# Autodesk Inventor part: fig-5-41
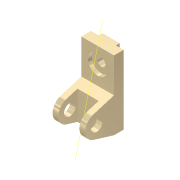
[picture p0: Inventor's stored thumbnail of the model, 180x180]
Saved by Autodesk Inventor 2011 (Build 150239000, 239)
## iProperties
Shininess: 65.0
Angle Display Precision: 2
Document Length Units: 11269
Document Angle Units: 11279
Document Time Units: 11290
Document Mass Units: 11283
Document Length Units Precision: 3
Document Angle Units Precision: 2
Created: 2001-11
Part Number: fig-5-41
Document SubType Name: Modeling
Designer: Renu Muthoo
Density: 1 g/cm^3
Density: 0.0
Volumn: 0.0
Area: 0.0
PropertySet Name: Model Information
Control State: 0
Master: False
Checked Out: False
Author: Renu Muthoo
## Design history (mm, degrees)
node "Sketch1"
sketch "Sketch2"
  geometry: L1 (33.257, 104.664)-(33.257, -75.336); L2 (33.257, -75.336)-(8.257, -75.336); L3 (8.257, -75.336)-(-45.451, -59.045); L4 (-45.451, -1.628)-(8.257, 14.664); L5 (8.257, 14.664)-(8.257, 104.664); L6 (8.257, 104.664)-(33.257, 104.664); C1 r 15 at (-36.743, -30.336); A1 r 30 centre (-36.743, -30.336) between (-45.451, -1.628) and (-45.451, -59.045)
  constraints: 12 end point, 2 centre point, 2 equal length, 2 parallel, 2 point on circle, 2 tangent, 1 coincident, 1 perpendicular, 1 vertical
  dimensions: "d0" = 180 distance of L1.start L1.end; "d1" = 30 radius of A1; "d2" = 25 distance of L5.end L1.start; "d3" = 45 distance from line of L2 A1.centre; "d4" = 70 distance from line of L1 A1.centre; "d5" = 30 diameter of C1
extrude "Extrusion1" new body sketch "Sketch2" distance "d6" = 85; taper "d7" = 0 deg
workplane "Work Plane1"
sketch "Sketch3"
  geometry: L1 (15, 62.364)-(70, 62.364); L2 (70, 62.364)-(70, -52.386); L3 (70, -52.386)-(15, -52.386); L4 (15, -52.386)-(15, 62.364); L5 (0, -45)-(0, -28.708) reference
  constraints: 8 end point, 2 parallel, 1 horizontal, 1 perpendicular
  dimensions: "d8" = 55 distance of L1.start L1.end; "d9" = 15 distance between parallel lines of L5 L4
extrude "Extrusion2" cut sketch "Sketch3" distance "d10" = 50; taper "d11" = 0 deg
sketch "Sketch4"
  geometry: L1 (0, 25)-(85, 25) reference; L2 (0, 0)-(0, 25) reference; L3 (20, 25)-(65, 25); L4 (65, 25)-(65, 35); L5 (65, 35)-(20, 35); L6 (20, 35)-(20, 25)
  constraints: 8 end point, 2 parallel, 1 horizontal, 1 perpendicular, 1 point on line
  dimensions: "d12" = 45 distance of L4.end L5.end; "d13" = 10 distance of L3.end L4.end; "d14" = 20 distance between parallel lines of L2 L6
extrude "Extrusion3" join sketch "Sketch4" stored distance "d15" = 50; taper "d16" = 0 deg
sketch "Sketch5"
  geometry: L1 (85, 0)-(85, 90) reference; L2 (0, 90)-(85, 90) reference; 1 further point
  dimensions: "d17" = 42 distance from line of L2 point (42.5, 48); "d18" = 42.5 distance from line of L1 point (42.5, 48)
hole "Hole1" sketch "Sketch5" at (42.5, 48) diameter "d19" = 20; stored, may be unused: countersink angle "d23" = 82 deg, drill point angle "d25" = 118 deg; dims "d20" = 6, "d21" = 50, "d22" = 10, "d24" = 8
workaxis "Work Axis1"
body "Solid1"
